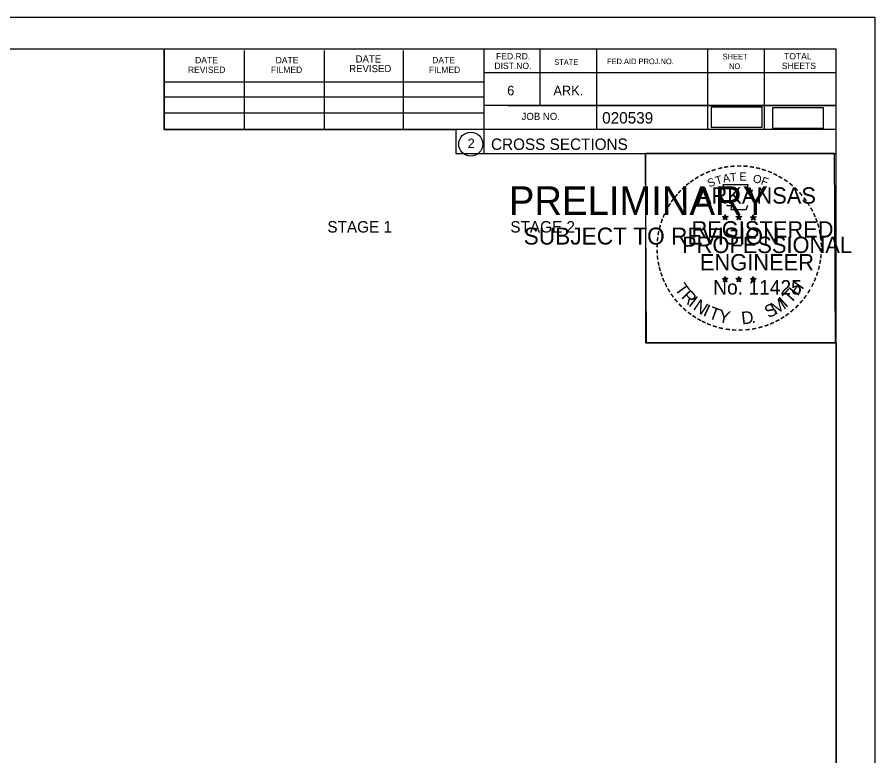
# Model space of a CAD drawing. Extents: x 915787 to 919910, y 133456 to 136717.
# Drawn here: x 916471.9 to 916576.9, y 135712.2 to 135802.7 of the extents above; entities that cross this region are included whole.
import ezdxf

# ---------------------------------------------------------------- set-up
doc = ezdxf.new("R2010")
doc.units = 0
for name, color, linetype in [('R_Border', 7, 'Continuous'), ('R_Border Notes', 7, 'Continuous'), ('R_Border PE', 7, 'Continuous'), ('R_Border Prem', 7, 'Continuous'), ('R_No Plot', 7, 'Continuous'), ('R_Xsect Slope', 7, 'Continuous')]:
    doc.layers.add(name, color=color, linetype=linetype)

msp = doc.modelspace()

# ---------------------------------------------------------------- linework, layer by layer
at = {"layer": 'R_Border'}
for p, q in [((916255.98, 135798.85), (916572.16, 135798.85)), ((916489.9, 135788.97), (916489.9, 135798.85)), ((916499.76, 135788.97), (916499.76, 135798.65)), ((916509.52, 135788.97), (916509.52, 135798.65)), ((916519.2, 135788.97), (916519.2, 135798.65)), ((916529.06, 135798.85), (916529.06, 135786.05)), ((916535.9, 135798.85), (916535.9, 135791.91)), ((916542.84, 135798.85), (916542.84, 135788.97)), ((916556.42, 135798.85), (916556.42, 135788.97)), ((916563.36, 135798.85), (916563.36, 135788.97)), ((916572.16, 135593.39), (916572.16, 135798.85)), ((916572.16, 135795.91), (916529.06, 135795.91)), ((916572.16, 135795.93), (916572.16, 135795.93)), ((916489.9, 135794.83), (916529.06, 135794.83)), ((916489.9, 135792.97), (916529.06, 135792.97)), ((916572.16, 135791.91), (916529.06, 135791.91)), ((916532.02, 135791.91), (916572.16, 135791.91)), ((916489.9, 135788.97), (916489.9, 135791.03)), ((916489.9, 135791.03), (916529.06, 135791.03)), ((916572.16, 135788.97), (916489.9, 135788.97)), ((916529.06, 135786.05), (916572.16, 135786.05))]:
    msp.add_line(p, q, dxfattribs=at)
msp.add_circle((916527.44, 135787.19), 1.47, dxfattribs=at)
at = {"layer": 'R_Border PE'}
for p, q in [((916558.59, 135778.56), (916558.55, 135778.31)), ((916558.59, 135778.2), (916558.59, 135778.56)), ((916558.59, 135778.56), (916558.64, 135778.31)), ((916560.26, 135778.56), (916560.22, 135778.31)), ((916560.26, 135778.2), (916560.26, 135778.56)), ((916560.26, 135778.56), (916560.31, 135778.31)), ((916562.02, 135778.55), (916561.98, 135778.3)), ((916562.02, 135778.19), (916562.02, 135778.55)), ((916562.02, 135778.55), (916562.07, 135778.3)), ((916558.24, 135778.31), (916558.59, 135778.2)), ((916558.24, 135778.31), (916558.49, 135778.26)), ((916558.24, 135778.31), (916558.48, 135778.19)), ((916558.37, 135777.9), (916558.59, 135778.2)), ((916558.37, 135777.9), (916558.5, 135778.15)), ((916558.37, 135777.9), (916558.59, 135778.12)), ((916558.94, 135778.31), (916558.59, 135778.2)), ((916558.8, 135777.9), (916558.59, 135778.2)), ((916558.8, 135777.9), (916558.59, 135778.12)), ((916558.94, 135778.31), (916558.65, 135778.26)), ((916558.8, 135777.9), (916558.66, 135778.19)), ((916558.94, 135778.31), (916558.73, 135778.21)), ((916559.91, 135778.31), (916560.26, 135778.2)), ((916559.91, 135778.31), (916560.16, 135778.26)), ((916559.91, 135778.31), (916560.15, 135778.19)), ((916560.04, 135777.9), (916560.26, 135778.2)), ((916560.04, 135777.9), (916560.17, 135778.15)), ((916560.04, 135777.9), (916560.26, 135778.12)), ((916560.61, 135778.31), (916560.26, 135778.2)), ((916560.47, 135777.9), (916560.26, 135778.2)), ((916560.47, 135777.9), (916560.26, 135778.12)), ((916560.61, 135778.31), (916560.32, 135778.26)), ((916560.47, 135777.9), (916560.33, 135778.19)), ((916560.61, 135778.31), (916560.4, 135778.21)), ((916561.67, 135778.3), (916562.02, 135778.19)), ((916561.67, 135778.3), (916561.93, 135778.25)), ((916561.67, 135778.3), (916561.91, 135778.18)), ((916561.81, 135777.89), (916562.02, 135778.19)), ((916561.81, 135777.89), (916561.93, 135778.13)), ((916561.81, 135777.89), (916562.02, 135778.11)), ((916562.37, 135778.3), (916562.02, 135778.19)), ((916562.24, 135777.89), (916562.02, 135778.19)), ((916562.24, 135777.89), (916562.02, 135778.1)), ((916562.37, 135778.3), (916562.08, 135778.25)), ((916562.24, 135777.89), (916562.1, 135778.18)), ((916562.37, 135778.3), (916562.17, 135778.2)), ((916558.24, 135770.74), (916558.58, 135770.63)), ((916558.24, 135770.74), (916558.49, 135770.69)), ((916558.24, 135770.74), (916558.47, 135770.61)), ((916558.37, 135770.33), (916558.58, 135770.63)), ((916558.37, 135770.33), (916558.49, 135770.57)), ((916558.37, 135770.33), (916558.58, 135770.55)), ((916558.58, 135770.99), (916558.54, 135770.74)), ((916558.58, 135770.63), (916558.58, 135770.99)), ((916558.58, 135770.99), (916558.63, 135770.74)), ((916558.93, 135770.74), (916558.58, 135770.63)), ((916558.8, 135770.33), (916558.58, 135770.63)), ((916558.8, 135770.33), (916558.58, 135770.54)), ((916558.93, 135770.74), (916558.65, 135770.69)), ((916558.8, 135770.33), (916558.66, 135770.62)), ((916558.93, 135770.74), (916558.73, 135770.63)), ((916559.9, 135770.74), (916560.25, 135770.63)), ((916559.9, 135770.74), (916560.16, 135770.69)), ((916559.9, 135770.74), (916560.14, 135770.61)), ((916560.04, 135770.33), (916560.25, 135770.63)), ((916560.04, 135770.33), (916560.16, 135770.57)), ((916560.04, 135770.33), (916560.25, 135770.55)), ((916560.25, 135770.99), (916560.21, 135770.74)), ((916560.25, 135770.63), (916560.25, 135770.99)), ((916560.25, 135770.99), (916560.3, 135770.74)), ((916560.6, 135770.74), (916560.25, 135770.63)), ((916560.47, 135770.33), (916560.25, 135770.63)), ((916560.47, 135770.33), (916560.25, 135770.54)), ((916560.6, 135770.74), (916560.31, 135770.69)), ((916560.47, 135770.33), (916560.33, 135770.62)), ((916560.6, 135770.74), (916560.4, 135770.63)), ((916561.67, 135770.73), (916562.02, 135770.62)), ((916561.67, 135770.73), (916561.92, 135770.68)), ((916561.67, 135770.73), (916561.91, 135770.6)), ((916561.8, 135770.32), (916562.02, 135770.62)), ((916561.8, 135770.32), (916561.93, 135770.56)), ((916561.8, 135770.32), (916562.02, 135770.54)), ((916562.02, 135770.98), (916561.98, 135770.73)), ((916562.02, 135770.62), (916562.02, 135770.98)), ((916562.02, 135770.98), (916562.07, 135770.73)), ((916562.37, 135770.73), (916562.02, 135770.62)), ((916562.23, 135770.32), (916562.02, 135770.62)), ((916562.23, 135770.32), (916562.02, 135770.53)), ((916562.37, 135770.73), (916562.08, 135770.68)), ((916562.23, 135770.32), (916562.1, 135770.61)), ((916562.37, 135770.73), (916562.16, 135770.62))]:
    msp.add_line(p, q, dxfattribs=at)
for points in [[(916558.28, 135782.19), (916558.55, 135781.36)], [(916561.79, 135781.27), (916561.93, 135781.55), (916561.25, 135781.53), (916561.4, 135782.19), (916558.28, 135782.19)], [(916558.77, 135779.76), (916558.77, 135779.68), (916559.34, 135779.66), (916559.28, 135779.19), (916561.15, 135779.19), (916561.35, 135779.72)], [(916558.59, 135778.56), (916558.8, 135777.9), (916558.24, 135778.31), (916558.94, 135778.31), (916558.37, 135777.9), (916558.59, 135778.56)], [(916560.26, 135778.56), (916560.47, 135777.9), (916559.91, 135778.31), (916560.61, 135778.31), (916560.04, 135777.9), (916560.26, 135778.56)], [(916562.02, 135778.55), (916562.24, 135777.89), (916561.67, 135778.3), (916562.37, 135778.3), (916561.81, 135777.89), (916562.02, 135778.55)], [(916558.58, 135770.99), (916558.8, 135770.33), (916558.24, 135770.74), (916558.93, 135770.74), (916558.37, 135770.33), (916558.58, 135770.99)], [(916560.25, 135770.99), (916560.47, 135770.33), (916559.9, 135770.74), (916560.6, 135770.74), (916560.04, 135770.33), (916560.25, 135770.99)], [(916562.02, 135770.98), (916562.23, 135770.32), (916561.67, 135770.73), (916562.37, 135770.73), (916561.8, 135770.32), (916562.02, 135770.98)]]:
    msp.add_lwpolyline(points, dxfattribs=at)
for centre, radius in [((916558.59, 135778.2), 0.172), ((916558.59, 135778.2), 0.145), ((916558.59, 135778.2), 0.116), ((916558.59, 135778.2), 0.0991), ((916558.59, 135778.2), 0.0747), ((916558.59, 135778.2), 0.0495), ((916558.59, 135778.2), 0.0296), ((916560.26, 135778.2), 0.172), ((916560.26, 135778.2), 0.145), ((916560.26, 135778.2), 0.116), ((916560.26, 135778.2), 0.0991), ((916560.26, 135778.2), 0.0747), ((916560.26, 135778.2), 0.0495), ((916560.26, 135778.2), 0.0296), ((916562.02, 135778.19), 0.172), ((916562.02, 135778.19), 0.145), ((916562.02, 135778.19), 0.116), ((916562.02, 135778.19), 0.0991), ((916562.02, 135778.19), 0.0747), ((916562.02, 135778.19), 0.0495), ((916562.02, 135778.19), 0.0296), ((916558.58, 135770.63), 0.172), ((916558.58, 135770.63), 0.145), ((916558.58, 135770.63), 0.116), ((916558.58, 135770.63), 0.0991), ((916558.58, 135770.63), 0.0747), ((916558.58, 135770.63), 0.0495), ((916558.58, 135770.63), 0.0296), ((916560.25, 135770.63), 0.172), ((916560.25, 135770.63), 0.145), ((916560.25, 135770.63), 0.116), ((916560.25, 135770.63), 0.0991), ((916560.25, 135770.63), 0.0747), ((916560.25, 135770.63), 0.0495), ((916560.25, 135770.63), 0.0296), ((916562.02, 135770.62), 0.172), ((916562.02, 135770.62), 0.145), ((916562.02, 135770.62), 0.116), ((916562.02, 135770.62), 0.0991), ((916562.02, 135770.62), 0.0747), ((916562.02, 135770.62), 0.0495), ((916562.02, 135770.62), 0.0296)]:
    msp.add_circle(centre, radius, dxfattribs=at)
at = {"layer": 'R_No Plot'}
for p, q in [((916243.57, 135802.75), (916576.91, 135802.75)), ((916548.19, 135763.6), (916548.19, 135763.6))]:
    msp.add_line(p, q, dxfattribs=at)
for points in [[(916243.57, 135802.75), (916576.91, 135802.75), (916576.91, 135589.41), (916243.57, 135589.41)], [(916489.9, 135798.85), (916489.9, 135788.97), (916525.63, 135788.97), (916525.63, 135786.05), (916548.83, 135786.05), (916548.83, 135762.84), (916572.16, 135762.84), (916572.16, 135593.39), (916255.98, 135593.39), (916255.98, 135798.85)], [(916548.83, 135786.09), (916571.92, 135786.09), (916572.04, 135762.84), (916548.94, 135762.84)]]:
    msp.add_lwpolyline(points, close=True, dxfattribs=at)
at = {"layer": 'R_Xsect Slope'}
for points in [[(916556.86, 135789.25), (916563.11, 135789.25), (916563.11, 135791.73), (916556.86, 135791.73)], [(916564.38, 135789.15), (916570.63, 135789.15), (916570.63, 135791.62), (916564.38, 135791.62)]]:
    msp.add_lwpolyline(points, close=True, dxfattribs=at)

# ---------------------------------------------------------------- texts
at = {"layer": 'R_Border'}
for s, height, p in [('DATE', 0.782, (916493.7, 135797.09)), ('DATE', 0.782, (916503.56, 135797.09)), ('DATE', 0.879, (916513.34, 135797.19)), ('DATE', 0.782, (916522.72, 135797.09)), ('FED.RD.', 0.782, (916530.54, 135797.57)), ('STATE', 0.684, (916537.66, 135796.89)), ('FED.AID PROJ.NO.', 0.684, (916544.12, 135796.99)), ('SHEET', 0.684, (916558.28, 135797.57)), ('TOTAL', 0.782, (916565.8, 135797.57)), ('REVISED', 0.782, (916492.82, 135795.91)), ('FILMED', 0.782, (916502.98, 135795.91)), ('REVISED', 0.879, (916512.56, 135796.01)), ('FILMED', 0.782, (916522.32, 135795.91)), ('DIST.NO.', 0.782, (916530.34, 135796.39)), ('NO.', 0.684, (916559.06, 135796.39)), ('SHEETS', 0.782, (916565.52, 135796.39)), ('6', 1.17, (916531.9, 135793.17)), ('ARK.', 1.172, (916537.56, 135793.17)), ('JOB NO.', 0.879, (916533.66, 135790.15)), ('020539', 1.4, (916543.53, 135789.71)), ('2', 1.17, (916527.06, 135786.7)), ('CROSS SECTIONS', 1.4, (916529.92, 135786.48))]:
    msp.add_text(s, height=height, rotation=360, dxfattribs=at).set_placement(p)
at = {"layer": 'R_Border Notes'}
for s, p in [('STAGE 1', (916509.89, 135776.36)), ('STAGE 2', (916532.29, 135776.36))]:
    msp.add_text(s, height=1.4, dxfattribs=at).set_placement(p)
at = {"layer": 'R_Border PE'}
for s, height, rotation, p in [('-', 1.6, 24.3072, (916556.39, 135783.05)), ('-', 1.6, 19.1761, (916557.03, 135783.31)), ('-', 1.6, 13.6301, (916557.78, 135783.56)), ('-', 1.6, 10.2193, (916558.46, 135783.72)), ('-', 1.6, 5.8968, (916559.19, 135783.83)), ('-', 1.6, 0.1862, (916559.96, 135783.9)), ('-', 1.6, 357.743, (916560.68, 135783.89)), ('-', 1.6, 352.1617, (916561.42, 135783.83)), ('-', 1.6, 347.2049, (916562.14, 135783.72)), ('-', 1.6, 342.3362, (916562.78, 135783.56)), ('-', 1.6, 337.8551, (916563.51, 135783.34)), ('-', 1.6, 36.2317, (916554.59, 135781.96)), ('-', 1.6, 34.0636, (916555.16, 135782.36)), ('-', 1.6, 28.7918, (916555.76, 135782.73)), ('S', 1, 21.594, (916556.64, 135781.87)), ('T', 1, 16.4036, (916557.55, 135782.2)), ('A', 1, 11.2132, (916558.38, 135782.45)), ('T', 1, 6.0228, (916559.22, 135782.61)), ('E', 1, 0.8323, (916560.33, 135782.72)), ('O', 1, 350.4515, (916561.93, 135782.51)), ('F', 1, 340.0707, (916562.89, 135782.29)), ('-', 1.6, 334.1211, (916564.14, 135783.07)), ('-', 1.6, 329.6409, (916564.72, 135782.78)), ('-', 1.6, 325.8627, (916565.37, 135782.42)), ('-', 1.6, 42.9622, (916553.68, 135781.17)), ('-', 1.6, 38.9507, (916554.11, 135781.59)), ('ARKANSAS', 2, 360, (916555.13, 135779.9)), ('-', 1.6, 320.5297, (916565.98, 135782)), ('-', 1.6, 315.5786, (916566.58, 135781.51)), ('-', 1.6, 50.6142, (916552.83, 135780.2)), ('-', 1.6, 48.423, (916553.23, 135780.69)), ('-', 1.6, 309.8797, (916567.14, 135780.96)), ('-', 1.6, 306.6522, (916567.67, 135780.36)), ('-', 1.6, 58.0706, (916552.09, 135779.11)), ('-', 1.6, 54.2325, (916552.41, 135779.64)), ('-', 1.4, 303.6753, (916568.16, 135779.79)), ('-', 1.6, 67.7743, (916551.52, 135777.89)), ('-', 1.6, 62.8713, (916551.78, 135778.5)), ('-', 1.6, 299.6684, (916568.47, 135779.18)), ('-', 1.6, 294.6628, (916568.8, 135778.57)), ('-', 1.6, 72.3945, (916551.3, 135777.26)), ('REGISTERED', 2, 360, (916554.46, 135775.75)), ('DWB', 0.01, 360, (916558.58, 135778.19)), ('DWB', 0.01, 360, (916560.25, 135778.19)), ('DWB', 0.01, 360, (916562.01, 135778.18)), ('-', 1.6, 290.5728, (916569.06, 135777.99)), ('-', 1.6, 285.1233, (916569.29, 135777.41)), ('-', 1.6, 81.2013, (916550.97, 135775.83)), ('-', 1.6, 75.461, (916551.1, 135776.54)), ('-', 1.6, 280.5493, (916569.49, 135776.67)), ('-', 1.6, 85.1863, (916550.89, 135775.14)), ('PROFESSIONAL', 2, 360, (916553.31, 135773.85)), ('-', 1.6, 276.5962, (916569.65, 135775.9)), ('-', 1.6, 89.0622, (916550.87, 135774.44)), ('-', 1.6, 274.3301, (916569.71, 135775.18)), ('-', 1.6, 269.9407, (916569.75, 135774.55)), ('-', 1.6, 94.1959, (916550.9, 135773.71)), ('-', 1.6, 98.9479, (916550.97, 135773.04)), ('ENGINEER', 2, 360, (916555.49, 135771.72)), ('-', 1.6, 263.5172, (916569.73, 135773.88)), ('-', 1.6, 101.7149, (916551.11, 135772.31)), ('-', 1.6, 255.7626, (916569.55, 135772.55)), ('-', 1.6, 260.9953, (916569.66, 135773.23)), ('-', 1.6, 105.4578, (916551.27, 135771.72)), ('-', 1.6, 109.0874, (916551.49, 135771.09)), ('-', 1.6, 252.8681, (916569.36, 135771.83)), ('-', 1.6, 114.0643, (916551.74, 135770.49)), ('-', 1.6, 115.7289, (916552.05, 135769.87)), ('T', 1.54, 306.0406, (916552.34, 135769.46)), ('No. 11425', 1.757, 360, (916557.12, 135768.77)), ('DWB', 0.01, 360, (916558.57, 135770.62)), ('DWB', 0.01, 360, (916560.24, 135770.62)), ('DWB', 0.01, 360, (916562.01, 135770.61)), ('H', 1.54, 54.6088, (916567.46, 135768.5)), ('-', 1.6, 244.6197, (916568.88, 135770.53)), ('-', 1.6, 247.8887, (916569.14, 135771.16)), ('-', 1.6, 120.4471, (916552.4, 135769.29)), ('R', 1.54, 314.005, (916553.11, 135768.42)), ('T', 1.54, 46.6444, (916566.58, 135767.56)), ('-', 1.6, 239.0712, (916568.49, 135769.78)), ('-', 1.6, 125.8934, (916552.81, 135768.72)), ('-', 1.6, 130.7181, (916553.27, 135768.17)), ('I', 1.54, 321.9694, (916554.01, 135767.48)), ('N', 1.54, 326.5002, (916554.57, 135767.01)), ('M', 1.54, 32.6563, (916564.73, 135766.23)), ('I', 1.54, 42.1136, (916566.01, 135767.08)), ('-', 1.6, 231.2538, (916567.65, 135768.56)), ('-', 1.6, 233.8452, (916568.08, 135769.12)), ('-', 1.6, 134.2238, (916553.78, 135767.63)), ('-', 1.6, 138.9338, (916554.31, 135767.16)), ('I', 1.54, 335.3603, (916555.78, 135766.23)), ('T', 1.54, 339.8912, (916556.44, 135765.9)), ('S', 1.54, 26.9312, (916563.89, 135765.83)), ('-', 1.6, 221.0851, (916566.65, 135767.49)), ('-', 1.6, 225.7653, (916567.17, 135767.99)), ('-', 1.6, 144.6463, (916554.87, 135766.76)), ('-', 1.6, 148.0898, (916555.43, 135766.39)), ('Y', 1.54, 347.8556, (916557.66, 135765.45)), ('D', 1.54, 6.3969, (916560.65, 135765.1)), ('-', 1.6, 212.2491, (916565.57, 135766.63)), ('-', 1.6, 215.7363, (916566.1, 135767.01)), ('-', 1.6, 151.5704, (916556.01, 135766.06)), ('-', 1.6, 154.6002, (916556.53, 135765.81)), ('-', 1.6, 158.5612, (916557.15, 135765.56)), ('-', 1.6, 162.7983, (916557.84, 135765.35)), ('.', 1.54, 13.7642, (916561.84, 135765.22)), ('-', 1.6, 195.4743, (916563.09, 135765.45)), ('-', 1.6, 200.7184, (916563.77, 135765.69)), ('-', 1.6, 204.2516, (916564.39, 135765.96)), ('-', 1.6, 207.3568, (916565.01, 135766.28)), ('-', 1.6, 167.5555, (916558.55, 135765.18)), ('-', 1.6, 173.1155, (916559.33, 135765.07)), ('-', 1.6, 176.5183, (916560.07, 135765.02)), ('-', 1.6, 181.5918, (916560.82, 135765.04)), ('-', 1.6, 185.8167, (916561.63, 135765.12)), ('-', 1.6, 191.2858, (916562.36, 135765.25))]:
    msp.add_text(s, height=height, rotation=rotation, dxfattribs=at).set_placement(p)
at = {"layer": 'R_Border Prem'}
for s, height, p in [('PRELIMINARY', 3.5, (916532.11, 135778.52)), ('DWB', 0.01, (916532.85, 135780.37)), ('SUBJECT TO REVISION', 2.0751, (916533.92, 135774.89))]:
    msp.add_text(s, height=height, rotation=360, dxfattribs=at).set_placement(p)

doc.saveas('drawing.dxf')
